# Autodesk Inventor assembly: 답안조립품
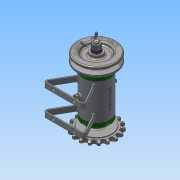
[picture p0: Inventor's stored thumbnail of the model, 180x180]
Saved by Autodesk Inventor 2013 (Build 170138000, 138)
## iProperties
Created: 2016-03
Part Number: 답안조립품
Document SubType Name: Weldment
Designer: Administrator
Weld Material: Welded Aluminum-6061
Author: Administrator
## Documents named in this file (16)
- C:\Users\Administrator\Desktop\460308V1017\답안조립품.iam
- C:\Users\Administrator\Desktop\460308V1017\본체.ipt
- C:\Users\Administrator\Desktop\460308V1017\베어링 15 x 32 x 9.ipt
- C:\Users\Administrator\Desktop\460308V1017\커버.ipt
- C:\Users\Administrator\Desktop\460308V1017\볼트 M 6 x 8.ipt
- C:\Users\Administrator\Desktop\460308V1017\볼트 M4 x 12.ipt
- C:\Users\Administrator\Desktop\460308V1017\오일 실 15 25 7.ipt
- C:\Users\Administrator\Desktop\460308V1017\축.ipt
- C:\Users\Administrator\Desktop\460308V1017\와셔 6x11.5.ipt
- C:\Users\Administrator\Desktop\460308V1017\니플 M 6 x 0.75.ipt
- C:\Users\Administrator\Desktop\460308V1017\키 3 x 3 x 12.ipt
- C:\Users\Administrator\Desktop\460308V1017\스프로킷.ipt
- C:\Users\Administrator\Desktop\460308V1017\와셔 8x17.ipt
- C:\Users\Administrator\Desktop\460308V1017\스프링와셔 8.ipt
- C:\Users\Administrator\Desktop\460308V1017\너트 M 8.ipt
- C:\Users\Administrator\Desktop\460308V1017\V벨트풀리.ipt
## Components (11 placed, 3 different names)
1. KS B 2023 6002 - 15 x 32 x 9:1
2. KS B 2023 6002 - 15 x 32 x 9:2
3. V벨트풀리:1
4. ISO 4762 M4 x 12:1
5. ISO 4762 M4 x 12:3
6. ISO 4762 M4 x 12:4
7. ISO 4762 M4 x 12:5
8. ISO 4762 M4 x 12:2
9. ISO 4762 M4 x 12:6
10. ISO 4762 M4 x 12:7
11. ISO 4762 M4 x 12:8
